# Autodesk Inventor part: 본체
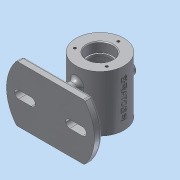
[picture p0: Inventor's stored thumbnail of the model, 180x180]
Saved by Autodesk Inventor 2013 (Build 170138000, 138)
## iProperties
Created: 2017-12
Part Number: 본체
Material: 알루미늄 6061
Document SubType Name: Modeling
Designer: dgall
Density: 2.71 g/cm^3
Mass: 467.691 g
Surface Area: 486.469 cm^2
Volume: 172.58 cm^3
Author: dgall
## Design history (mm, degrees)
sketch "스케치1"
  geometry: C1 r 30 at (0, 0); 1 further point
  constraints: 1 centre point, 1 coincident
  dimensions: "d0" = 60 diameter of C1
extrude "돌출1" new body sketch "스케치1" stored distance "d2" = 70; taper "d3" = 0 deg
node "작업 평면1"
node "작업 평면2"
node "작업 평면3"
node "작업 평면4"
sketch "스케치5"
  geometry: C1 r 8 at (0, 0); 1 further point
  constraints: 1 centre point, 1 coincident
  dimensions: "d23" = 16 diameter of C1
extrude "돌출5" join sketch "스케치5" stored distance "d25" = 10; taper "d26" = 0 deg
node "작업 평면5"
sketch "스케치6"
  geometry: L1 (30, 35)-(-30, 35) reference; L2 (-30, -35)-(30, -35) reference; L3 (0, 35)-(0, -35); L4 (16, 35)-(16, 23.3); L5 (15.7, 23)-(14, 23); L6 (14, 23)-(14, 20); L7 (14, 20)-(22, 20); L8 (25, 17)-(25, -17); L9 (22, -20)-(14, -20); L10 (14, -20)-(14, -23); L11 (14, -23)-(15.7, -23); L12 (16, -23.3)-(16, -35); L13 (16, 35)-(0, 35); L14 (16, -35)-(0, -35); A1 r 3 centre (22, -17) between (22, -20) and (25, -17); A2 r 3 centre (22, 17) between (25, 17) and (22, 20); A3 r 0.3 centre (15.7, 23.3) between (15.7, 23) and (16, 23.3); A4 r 0.3 centre (15.7, -23.3) between (16, -23.3) and (15.7, -23); 5 further points
  constraints: 24 end point, 10 point on line, 8 point on circle, 8 tangent, 7 parallel, 4 centre point, 3 collinear, 2 equal radius, 2 midpoint, 2 perpendicular, 2 vertical alignment
  dimensions: "d27" = 32 diameter of L4 L3; "d29" = 28 diameter of L6 L3; "d30" = 50 diameter of L8 L3; "d31" = 40 distance of point (25, 20) point (25, -20); "d32" = 12 distance of point (16, -23) L12.end; "d33" = 3 distance of L9.end L10.end; "d34" = 3 radius of A1; "d35" = 0.3 radius of A3
revolve "회전1" sketch "스케치6" stored, may be unused: angle "d36" = 90 deg
chamfer "모따기1" distance "d37" = 1; stored, may be unused: second distance "d38" = 2, angle "d39" = 45 deg
chamfer "모따기2" distance "d40" = 1; stored, may be unused: second distance "d41" = 2, angle "d42" = 45 deg
hole "구멍1" diameter "d45" = 8; stored, may be unused: countersink angle "d49" = 90 deg, drill point angle "d51" = 0 deg; dims "d43" = 10, "d44" = 10, "d46" = 6, "d47" = 4, "d48" = 2, "d50" = 25
chamfer "모따기3" distance "d52" = 1; stored, may be unused: second distance "d53" = 2, angle "d54" = 45 deg
fillet "모깎기1" dims "d55" = 3
sketch "스케치7"
  geometry: L1 (-42.426, 35)-(42.426, 35); L2 (-42.426, -35)-(42.426, -35); A1 r 55 centre (0, 0) between (-42.426, 35) and (-42.426, -35); A2 r 55 centre (0, 0) between (42.426, -35) and (42.426, 35); 3 further points
  constraints: 4 end point, 4 point on circle, 2 centre point, 2 coincident, 2 concentric, 2 midpoint, 2 parallel, 2 vertical alignment, 1 horizontal
  dimensions: "d58" = 70 distance between parallel lines of L2 L1; "d59" = 110 diameter of A1
extrude "돌출6" join sketch "스케치7" distance "d60" = 10; taper "d61" = 0 deg
sketch "스케치8"
  geometry: L1 (-40, 5)-(-24, 5); L2 (-40, -5)-(-24, -5); L3 (-5, 15)-(-5, -15); L4 (5, 15)-(5, -15); A1 r 55 centre (0, 0) between (42.426, -35) and (42.426, 35) reference; A2 r 5 centre (-40, 0) between (-40, 5) and (-40, -5); A3 r 5 centre (-24, 0) between (-24, -5) and (-24, 5); A4 r 5 centre (0, 15) between (5, 15) and (-5, 15); A5 r 5 centre (0, -15) between (-4.969, -14.448) and (5, -15)
  constraints: 9 point on circle, 8 end point, 4 centre point, 4 tangent, 3 parallel, 2 equal radius, 2 horizontal alignment, 2 vertical alignment, 1 vertical
  dimensions: "d62" = 5 radius of A2; "d64" = 24 distance of A1.centre A3.centre; "d65" = 40 distance of A1.centre A2.centre; "d66" = 5 radius of A4; "d67" = 30 distance of A5.centre A4.centre; "d68" = 15 distance of A1.centre A4.centre
extrude "돌출7" join sketch "스케치8" stored distance "d69" = 10; taper "d70" = 0 deg
extrude "돌출8" cut sketch "스케치8" stored distance "d71" = 10; taper "d72" = 0 deg
sketch "스케치9" dims "d73" = 46
  geometry: L1 (0, 0)-(0, 23); C1 r 17 at (0, 0) reference
  constraints: 2 end point, 1 coincident, 1 vertical, 1 vertical alignment, 2 other
hole "구멍2" sketch "스케치9" at (0, 23) diameter "d75" = 3.242; stored, may be unused: countersink angle "d79" = 90 deg, drill point angle "d81" = 118 deg; dims "d76" = 8, "d77" = 4, "d78" = 2, "d80" = 10
fillet "모깎기2" dims "d85" = 5
fillet "모깎기3" dims "d86" = 3
fillet "모깎기4" dims "d87" = 3
node "작업 평면7"
  node "작업 평면6"
sketch "스케치10"
  geometry: L1 (30, 35)-(-30, 35) reference; 2 further points
  constraints: 1 other
  dimensions: "d89" = 35 distance from line of L1 point (0, 0); "d90" = 30 horizontal distance of L1.start point (0, 0)
feature "엠보싱1" sketch "스케치10" dims "d2" = 70, "d27" = 32, "d29" = 28, "d30" = 50, "d31" = 40, "d32" = 12, "d33" = 3, "d34" = 3, "d35" = 0.3, "d91" = 0.5, "d92" = 0
node "솔리드1"
mirror "대칭2"
pattern_circular "원형 패턴1" dims angle "d83" = 360 deg
mirror "대칭3"
other parameters: "d4" = -62, "d22" = 37
